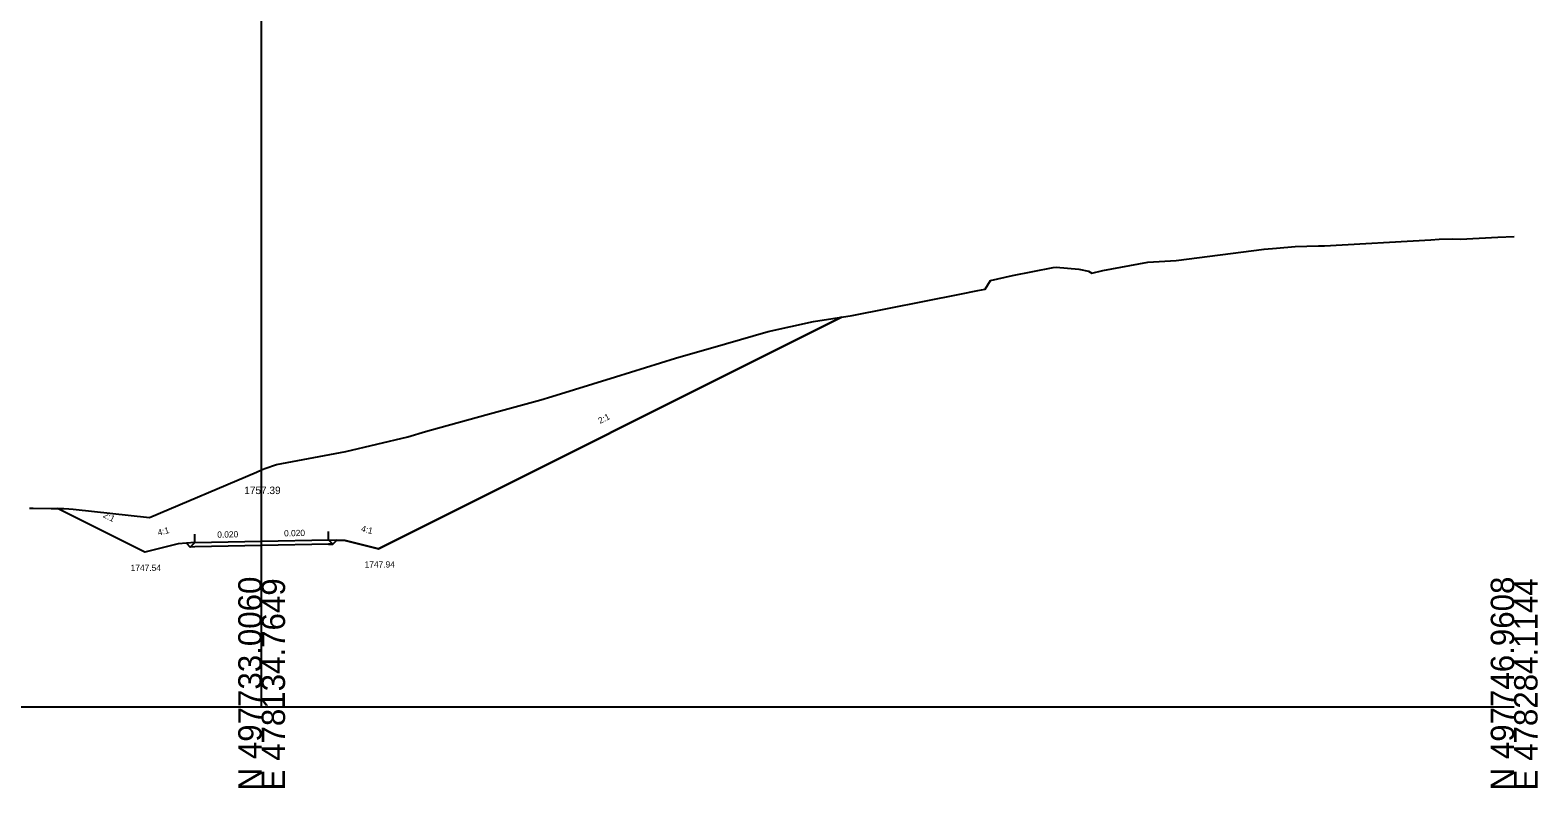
# Model space of a CAD drawing. Extents: x -26 to 303, y -10 to 3689.
# Drawn here: x 122.3 to 302.8, y 1990.3 to 2081.1 of the extents above; entities that cross this region are included whole.
import ezdxf

# ---------------------------------------------------------------- set-up
doc = ezdxf.new("R2010")
doc.units = 0
for name, color, linetype in [('Exist Cross Section Cell', 7, 'Continuous'), ('Exist XS Center Line Elevation Label', 7, 'Continuous'), ('Exist XS Ground Line', 7, 'Continuous'), ('Prop XS Ditch Slope Text', 7, 'Continuous'), ('Prop XS Ditch Standard Text', 7, 'Continuous'), ('Prop XS Dump Level', 7, 'Continuous'), ('Prop XS Earthwork Shape', 7, 'Continuous'), ('Prop XS EOT Tick Mark', 7, 'Continuous'), ('Prop XS Finish Grade', 7, 'Continuous'), ('Prop XS Finish Grade Earthwork', 7, 'Continuous'), ('Prop XS Finish Grade Pavement', 7, 'Continuous'), ('Prop XS Hydro Typical Ditch Data', 7, 'Continuous'), ('Prop XS Pvmt Edge Slope', 7, 'Continuous'), ('Prop XS SE Text', 7, 'Continuous'), ('Prop XS Shoulder Borrow Shape', 7, 'Continuous'), ('Prop XS Side Slope Text', 7, 'Continuous'), ('Prop XS Subgrade Earthwork', 7, 'Continuous')]:
    doc.layers.add(name, color=color, linetype=linetype)

msp = doc.modelspace()

# ---------------------------------------------------------------- linework, layer by layer
at = {"layer": 'Exist Cross Section Cell'}
for p, q in [((150, 2000), (150, 2168.96)), ((0, 2000), (150, 2000)), ((150, 2000), (300, 2000))]:
    msp.add_line(p, q, dxfattribs=at)
at = {"layer": 'Exist XS Ground Line'}
msp.add_lwpolyline([(122.19, 2023.81), (122.64, 2023.8), (124.79, 2023.78), (125.17, 2023.77), (126.29, 2023.75), (126.92, 2023.74), (127.41, 2023.68), (136.55, 2022.67), (149.39, 2028.12), (150, 2028.39), (150.4, 2028.56), (151.77, 2029.03), (160.09, 2030.58), (167.49, 2032.35), (169.62, 2032.97), (171.07, 2033.38), (177.29, 2035.12), (183.45, 2036.79), (184.76, 2037.17), (192.37, 2039.52), (199.55, 2041.76), (205.54, 2043.47), (210.67, 2044.95), (216.08, 2046.14), (220.72, 2046.86), (233.63, 2049.43), (235.78, 2049.88), (236.65, 2050.02), (237.3, 2051.09), (239.92, 2051.66), (244.78, 2052.61), (245.15, 2052.65), (247.88, 2052.43), (249.02, 2052.19), (249.42, 2051.94), (250.74, 2052.26), (256.13, 2053.27), (259.51, 2053.45), (270.06, 2054.83), (271.54, 2054.96), (273.76, 2055.16), (276.57, 2055.23), (277.3, 2055.24), (290.04, 2055.96), (291.03, 2056.02), (292.58, 2056.08), (293.58, 2056.04), (298.04, 2056.27), (300, 2056.32)], dxfattribs=at)
at = {"layer": 'Prop XS Dump Level'}
for p, q in [((142, 2019.7), (150, 2019.86)), ((150, 2019.86), (158, 2020.02))]:
    msp.add_line(p, q, dxfattribs=at)
at = {"layer": 'Prop XS Earthwork Shape'}
msp.add_lwpolyline([(158, 2019.48), (150, 2019.32), (142, 2019.16), (141.45, 2019.15), (140.98, 2019.62), (140, 2019.54), (136, 2018.54), (125.56, 2023.76), (126.29, 2023.75), (126.92, 2023.74), (127.41, 2023.68), (136.55, 2022.67), (149.39, 2028.12), (150, 2028.39), (150.4, 2028.56), (151.77, 2029.03), (160.09, 2030.58), (167.49, 2032.35), (169.62, 2032.97), (171.07, 2033.38), (177.29, 2035.12), (183.45, 2036.79), (184.76, 2037.17), (192.37, 2039.52), (199.55, 2041.76), (205.54, 2043.47), (210.67, 2044.95), (216.08, 2046.14), (219.44, 2046.66), (164, 2018.94), (160, 2019.94), (159.02, 2019.98), (158.53, 2019.49)], close=True, dxfattribs=at)
msp.add_lwpolyline([(158, 2019.48), (150, 2019.32), (142, 2019.16), (141.45, 2019.15), (140.98, 2019.62), (140, 2019.54), (136, 2018.54), (125.56, 2023.76), (126.29, 2023.75), (126.92, 2023.74), (127.41, 2023.68), (136.55, 2022.67), (149.39, 2028.12), (150, 2028.39), (150.4, 2028.56), (151.77, 2029.03), (160.09, 2030.58), (167.49, 2032.35), (169.62, 2032.97), (171.07, 2033.38), (177.29, 2035.12), (183.45, 2036.79), (184.76, 2037.17), (192.37, 2039.52), (199.55, 2041.76), (205.54, 2043.47), (210.67, 2044.95), (216.08, 2046.14), (219.44, 2046.66), (164, 2018.94), (160, 2019.94), (159.02, 2019.98), (158.53, 2019.49)], close=True, dxfattribs=at)
at = {"layer": 'Prop XS EOT Tick Mark'}
for p, q in [((142, 2019.7), (142, 2020.7)), ((158, 2020.02), (158, 2021.02))]:
    msp.add_line(p, q, dxfattribs=at)
at = {"layer": 'Prop XS Finish Grade'}
for p, q in [((142, 2019.7), (140.98, 2019.62)), ((158, 2020.02), (159.02, 2019.98))]:
    msp.add_line(p, q, dxfattribs=at)
at = {"layer": 'Prop XS Finish Grade Earthwork'}
for p, q in [((164, 2018.94), (219.44, 2046.66)), ((136, 2018.54), (125.56, 2023.76)), ((140, 2019.54), (136, 2018.54)), ((140.98, 2019.62), (140, 2019.54)), ((159.02, 2019.98), (160, 2019.94)), ((160, 2019.94), (164, 2018.94))]:
    msp.add_line(p, q, dxfattribs=at)
at = {"layer": 'Prop XS Finish Grade Pavement'}
for p, q in [((142, 2019.7), (150, 2019.86)), ((150, 2019.86), (158, 2020.02))]:
    msp.add_line(p, q, dxfattribs=at)
at = {"layer": 'Prop XS Hydro Typical Ditch Data'}
for p, q in [((136, 2018.54), (125.56, 2023.76)), ((140, 2019.54), (136, 2018.54))]:
    msp.add_line(p, q, dxfattribs=at)
at = {"layer": 'Prop XS Pvmt Edge Slope'}
for p, q in [((142, 2019.7), (141.45, 2019.15)), ((158, 2020.02), (158.53, 2019.49))]:
    msp.add_line(p, q, dxfattribs=at)
at = {"layer": 'Prop XS Shoulder Borrow Shape'}
for points in [[(142, 2019.7), (140.98, 2019.62), (141.45, 2019.15)], [(158, 2020.02), (159.02, 2019.98), (158.53, 2019.49)]]:
    msp.add_lwpolyline(points, close=True, dxfattribs=at)
at = {"layer": 'Prop XS Subgrade Earthwork'}
for p, q in [((141.45, 2019.15), (140.98, 2019.62)), ((142, 2019.16), (141.45, 2019.15)), ((150, 2019.32), (142, 2019.16)), ((158, 2019.48), (150, 2019.32)), ((158, 2019.48), (158.53, 2019.49)), ((158.53, 2019.49), (159.02, 2019.98))]:
    msp.add_line(p, q, dxfattribs=at)

# ---------------------------------------------------------------- texts
at = {"layer": 'Exist Cross Section Cell'}
for s, p in [('N 497733.0060', (150, 1990)), ('E 478134.7649', (152.8, 1990)), ('N 497746.9608', (300, 1990)), ('E 478284.1144', (302.8, 1990))]:
    msp.add_text(s, height=2.8, rotation=90, dxfattribs=at).set_placement(p)
at = {"layer": 'Exist XS Center Line Elevation Label'}
msp.add_text('1757.39', height=0.9, dxfattribs=at).set_placement((147.92, 2025.49))
at = {"layer": 'Prop XS Ditch Slope Text'}
for rotation, p in [(14.0362, (137.64, 2020.5)), (345.9638, (161.85, 2021.03))]:
    msp.add_text('4:1', height=0.75, rotation=rotation, dxfattribs=at).set_placement(p)
at = {"layer": 'Prop XS Ditch Standard Text'}
for s, p in [('1747.54', (134.31, 2016.29)), ('1747.94', (162.33, 2016.69))]:
    msp.add_text(s, height=0.75, dxfattribs=at).set_placement(p)
at = {"layer": 'Prop XS Dump Level'}
for p in [(140, 2019.5), (160, 2019.9)]:
    msp.add_text('Case1', height=0.04, dxfattribs=at).set_placement(p)
at = {"layer": 'Prop XS SE Text'}
for p in [(144.69, 2020.26), (152.69, 2020.42)]:
    msp.add_text('0.020', height=0.75, rotation=1.1458, dxfattribs=at).set_placement(p)
at = {"layer": 'Prop XS Side Slope Text'}
for rotation, p in [(26.5651, (190.54, 2033.89)), (333.4349, (130.94, 2022.75))]:
    msp.add_text('2:1', height=0.75, rotation=rotation, dxfattribs=at).set_placement(p)

doc.saveas('drawing.dxf')
